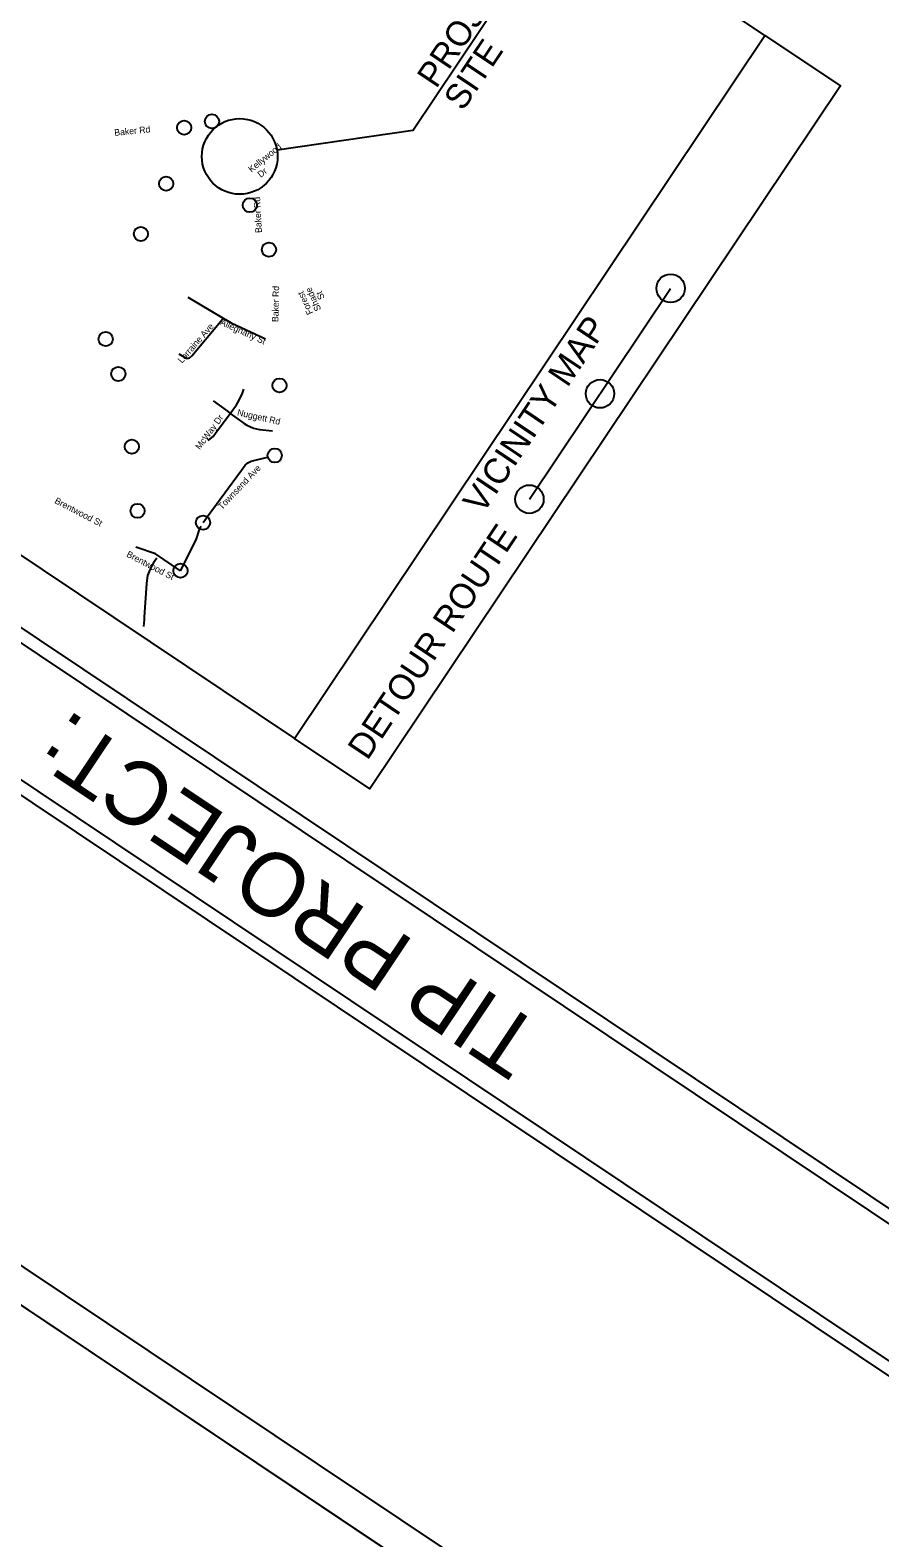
# Model space of a CAD drawing. Extents: x 1715610 to 1720914, y 798298 to 802505.
# Drawn here: x 1716488 to 1716990, y 799944 to 800836 of the extents above; entities that cross this region are included whole.
import ezdxf

# ---------------------------------------------------------------- set-up
doc = ezdxf.new("R2010")
doc.units = 0
for name, color, linetype in [('Default', 7, 'Continuous'), ('Prop DSN Text', 7, 'Continuous'), ('Sheet Cutting Line CELL', 7, 'Continuous'), ('Sheet Plot Border Inside CELL', 7, 'Continuous'), ('Sheet Plot Border Outside CELL', 7, 'Continuous'), ('Sheet Title CELL', 7, 'Continuous')]:
    doc.layers.add(name, color=color, linetype=linetype)

msp = doc.modelspace()

# ---------------------------------------------------------------- linework, layer by layer
at = {"layer": 'Default'}
for p, q in [((1716581.21, 800678.01), (1716594.89, 800669.76)), ((1716594.89, 800669.76), (1716602.08, 800665.55)), ((1716583.74, 800643.23), (1716600.78, 800663.65)), ((1716600.78, 800663.65), (1716601.76, 800664.92)), ((1716601.76, 800664.92), (1716602.08, 800665.55)), ((1716602.08, 800665.55), (1716606.96, 800662.77)), ((1716606.96, 800662.77), (1716627.29, 800653.32)), ((1716575.89, 800644.42), (1716580.35, 800641.87)), ((1716580.35, 800641.87), (1716580.88, 800641.74)), ((1716580.88, 800641.74), (1716582.33, 800642.04)), ((1716582.33, 800642.04), (1716582.78, 800642.38)), ((1716582.78, 800642.38), (1716583.74, 800643.23)), ((1716596.26, 800616.58), (1716604.77, 800610.44)), ((1716610.07, 800614.22), (1716611.66, 800617.02)), ((1716611.66, 800617.02), (1716613.69, 800621.21)), ((1716613.69, 800621.21), (1716614.37, 800623.46)), ((1716597.71, 800597.43), (1716606.39, 800609.18)), ((1716604.77, 800610.44), (1716606.39, 800609.18)), ((1716606.39, 800609.18), (1716610.07, 800614.22)), ((1716606.39, 800609.18), (1716614.68, 800603.16)), ((1716596.26, 800595.58), (1716597.71, 800597.43)), ((1716614.68, 800603.16), (1716616.19, 800602.25)), ((1716616.19, 800602.25), (1716617.85, 800601.43)), ((1716617.85, 800601.43), (1716620.1, 800600.52)), ((1716620.1, 800600.52), (1716623.58, 800599.6)), ((1716623.58, 800599.6), (1716631.29, 800598.79)), ((1716593.06, 800593.28), (1716594.52, 800594.16)), ((1716594.52, 800594.16), (1716596.26, 800595.58)), ((1716615.17, 800578.63), (1716616.79, 800579.98)), ((1716616.79, 800579.98), (1716618.75, 800580.96)), ((1716618.75, 800580.96), (1716629.18, 800583.57)), ((1716593.31, 800548.89), (1716615.17, 800578.63)), ((1716590.26, 800544.62), (1716593.31, 800548.89)), ((1716583.99, 800530.03), (1716586.42, 800535.07)), ((1716586.42, 800535.07), (1716588.23, 800540.46)), ((1716588.23, 800540.46), (1716589.14, 800542.6)), ((1716562.17, 800526.17), (1716550.51, 800530.1)), ((1716576.98, 800516.2), (1716562.17, 800526.17)), ((1716576.98, 800516.2), (1716583.99, 800530.03)), ((1716559.39, 800518.07), (1716557.95, 800514.79)), ((1716561.05, 800520.92), (1716559.39, 800518.07)), ((1716562.88, 800523.56), (1716561.05, 800520.92)), ((1716556.82, 800508.62), (1716555.54, 800488.79)), ((1716557.18, 800511.89), (1716556.82, 800508.62)), ((1716557.51, 800513.37), (1716557.18, 800511.89)), ((1716557.95, 800514.79), (1716557.51, 800513.37)), ((1716555.52, 800487.22), (1716555.17, 800483.29)), ((1716555.54, 800488.79), (1716555.52, 800487.22))]:
    msp.add_line(p, q, dxfattribs=at)
msp.add_circle((1716611.96, 800761.1), 22.37, dxfattribs=at)
at = {"layer": 'Prop DSN Text'}
for p, q in [((1716714.33, 800776.43), (1716778.91, 800872.91)), ((1716714.33, 800776.43), (1716634.02, 800764.8)), ((1716783.23, 800558.46), (1716866.67, 800683.12))]:
    msp.add_line(p, q, dxfattribs=at)
for points in [[(1716644.27, 800417.02), (1716922.46, 800832.66), (1716560.18, 801075.15), (1716281.98, 800659.5)], [(1716644.27, 800417.02), (1716922.46, 800832.66), (1716967.08, 800802.8), (1716688.88, 800387.16)]]:
    msp.add_lwpolyline(points, close=True, dxfattribs=at)
for centre, radius in [((1716595.52, 800781.84), 4.2), ((1716579.14, 800778.13), 4.2), ((1716568.5, 800744.98), 4.2), ((1716617.95, 800732.3), 4.2), ((1716553.54, 800715.28), 4.2), ((1716629.25, 800706), 4.2), ((1716866.67, 800683.12), 8.4), ((1716532.72, 800653.12), 4.2), ((1716540.2, 800632.51), 4.2), ((1716635.47, 800625.72), 4.2), ((1716824.95, 800620.79), 8.4), ((1716548.18, 800589.58), 4.2), ((1716632.68, 800584.31), 4.2), ((1716783.23, 800558.46), 8.4), ((1716551.57, 800551.59), 4.2), ((1716590.26, 800544.62), 4.2), ((1716576.98, 800516.2), 4.2)]:
    msp.add_circle(centre, radius, dxfattribs=at)
at = {"layer": 'Sheet Cutting Line CELL'}
msp.add_line((1715998.48, 800405.98), (1717369.67, 799488.23), dxfattribs=at)
at = {"layer": 'Sheet Plot Border Inside CELL'}
msp.add_lwpolyline([(1717352.55, 799523.15), (1718742.97, 801600.53), (1717427.73, 802480.84), (1716037.32, 800403.46)], close=True, dxfattribs=at)
at = {"layer": 'Sheet Plot Border Outside CELL'}
msp.add_lwpolyline([(1717403.5, 802505.18), (1715998.48, 800405.98), (1717369.67, 799488.23), (1718774.69, 801587.42)], close=True, dxfattribs=at)
at = {"layer": 'Sheet Title CELL'}
for p, q in [((1717500.86, 799792.1), (1716229.38, 800643.12)), ((1717274.42, 799952.69), (1716233.55, 800649.36))]:
    msp.add_line(p, q, dxfattribs=at)
for points in [[(1716181.43, 800584.97), (1717465.38, 799725.6)], [(1716181.43, 800584.97), (1717465.38, 799725.6)], [(1716191.85, 800587.04), (1717463.32, 799736.01)]]:
    msp.add_lwpolyline(points, dxfattribs=at)

# ---------------------------------------------------------------- texts
at = {"layer": 'Default'}
for s, height, rotation, p in [('Baker Rd', 3.83, 5.63289, (1716538.02, 800773.27)), ('Kellywood', 3.83, 39.32041, (1716618.97, 800751.41)), (' Dr', 3.83, 39.32041, (1716623.3, 800747.48)), ('Baker Rd', 3.83, 93.08223, (1716625.11, 800715.98)), ('Baker Rd', 3.83, 88.7702, (1716634.82, 800663.19)), ('Forest', 3.83, 114.51831, (1716655.47, 800668.58)), (' Shade', 3.83, 114.51831, (1716660.8, 800669.37)), (' St', 3.83, 114.51831, (1716662.93, 800676.15)), ('Lorraine Ave', 3.8304, 48.91699, (1716577.83, 800638.56)), ('Alleghany St', 3.8304, 335.53821, (1716600.1, 800661.76)), ('McWay Dr', 3.83, 53.60524, (1716588.44, 800587.44)), ('Nuggett Rd', 3.83, 347.23861, (1716610.22, 800608.09)), ('Townsend Ave', 3.8304, 46.51082, (1716601.47, 800551.98)), ('Brentwood St', 3.8304, 332.62893, (1716502.16, 800556.33)), ('Brentwood St', 3.8304, 332.62893, (1716544.65, 800524.7))]:
    msp.add_text(s, height=height, rotation=rotation, dxfattribs=at).set_placement(p)
at = {"layer": 'Prop DSN Text'}
for s, height, p in [('PROJECT ', 14.701, (1716728.14, 800800.7)), ('SITE', 14.701, (1716743.94, 800787.44)), ('VICINITY MAP', 15, (1716755.5, 800549.02)), ('DETOUR ROUTE', 15, (1716687.39, 800403.53))]:
    msp.add_text(s, height=height, rotation=56.20506, dxfattribs=at).set_placement(p)
at = {"layer": 'Sheet Title CELL'}
msp.add_text('TIP PROJECT:', height=37.5, rotation=146.20506, dxfattribs=at).set_placement((1716792.69, 800245.54))

doc.saveas('drawing.dxf')
